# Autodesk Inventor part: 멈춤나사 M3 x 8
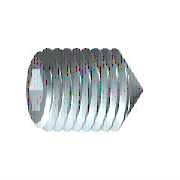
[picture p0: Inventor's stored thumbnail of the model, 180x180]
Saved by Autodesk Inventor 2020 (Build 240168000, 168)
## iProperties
Created: 2012-02
Part Number: 멈춤나사 M3 x 8
Material: 강철, 연강
Description: 6각 소켓 머리 없는 멈춤 나사
Document SubType Name: Modeling
Standard: KS B 1028
Designer: test
Standards Organization: KS
Language: ko-KR
Size Designation: 원추점 M3x8
Categories: <MemberInstance><Categories><Category DisplayName="조임쇠" InternalName="e4da775c-781d-43d5-af7c-5136215cf5a6" Mnemonic="FSTN"><Category DisplayName="볼트" InternalN
Density: 1 g/cm^3
Appearance: 강철
IsCustomPart: 1
Author: test
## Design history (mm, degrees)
sketch "스케치1"
  geometry: L1 (0, 0)-(5.5, 0); L2 (8, 0.866)-(8, 1.5); L3 (8, 1.5)-(0, 1.5); L4 (8, 0.866)-(6, 0.866); L5 (6, 0.866)-(5.5, 0); L6 (0, -0.3)-(0, 1.8) reference; L7 (0, 1.5)-(0, 0)
  constraints: 13 end point, 3 parallel, 1 collinear, 1 perpendicular, 1 point on line
  dimensions: "d0" = 2 distance of L2.start L4.end (= INTI); "d1" = 60 deg angle of L5 L1; "d2" = 3 diameter of L3 L1 (= NND); "d3" = 1.73205 diameter of L4 L1 (= 1.1547 x SW); "d5" = 8 distance from line of L2 L3.end (= NLG)
revolve "본체" sketch "스케치1" stored, may be unused: angle "d6" = 90 deg
sketch "스케치2"
  geometry: L1 (-0.433, 0.75)-(0.433, 0.75); L2 (0.433, 0.75)-(0.866, 0); L3 (0.866, 0)-(0.433, -0.75); L4 (0.433, -0.75)-(-0.433, -0.75); L5 (-0.433, -0.75)-(-0.866, 0); L6 (-0.866, 0)-(-0.433, 0.75); 3 further points
  constraints: 12 end point, 1 coincident, 1 horizontal, 13 other
extrude "슬롯" join sketch "스케치2" taper "d7" = 0 deg; stored distance "d21" = 10
workaxis "Work Axis1"
workplane "Work Plane1"
sketch "스케치4"
  geometry: L1 (0, 0.15)-(-1.35, 1.5) reference; L2 (0, -0.15)-(-1.35, -1.5) reference; L3 (-1.35, -1.5)-(0.15, 0); L4 (-1.35, 1.5)-(0.15, 0); 2 further points
  constraints: 4 end point, 1 coincident, 1 collinear, 1 horizontal alignment
body "Solid1"
feature "스레드" dims "d12" = 8 (= NLG), "d13" = 0
chamfer "모따기1" distance "d8" = 1.35 (computed from NND, SPD, FAWI); stored, may be unused: angle "d9" = 45 deg (= FAWI), second distance "d34" = 1.35 (computed from NND, SPD, FAWI)
chamfer "모따기2" distance "d10" = 0.30673 (= -0.5 x GD1 + 0.5 x NND); stored, may be unused: angle "d11" = 45 deg (= FAWI), second distance "d35" = 0.30673 (= -0.5 x GD1 + 0.5 x NND)
other parameters: "NND" = 3 [user parameter; used in 5 equation terms], "NLG" = 8 [user parameter; used in 2 equation terms], "INTI" = 2 [user parameter; used in 1 equation term], "FAWI" = 45 deg [user parameter; used in 4 equation terms], "SW" = 1.5 [user parameter; used in 2 equation terms], "GD1" = 2.38655 (= THREADDIA - 1.2269 x PTC) [user parameter; used in 2 equation terms], "d4" = 0, "FAWI1" = 45 deg [user parameter], "SPD" = 0.3 [user parameter; used in 2 equation terms], "d36" = 0, "d37" = 0, "GUL" = 0.30673 (= 0.61345 x PTC) [user parameter], "TOA" = 30 deg [user parameter], "THREADDIA" = 3 [user parameter; used in 1 equation term], "PTC" = 0.5 [user parameter; used in 4 equation terms], "GAL" = 0.30673 (= 0.61345 x PTC) [user parameter], "E0" = 1.7325 (= 1.155 x SW) [user parameter]
